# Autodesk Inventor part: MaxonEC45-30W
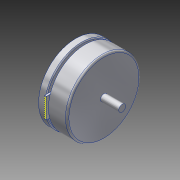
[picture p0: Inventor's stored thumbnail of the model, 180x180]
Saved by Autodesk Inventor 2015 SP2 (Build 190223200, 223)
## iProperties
Created: 2012-07
Part Number: MaxonEC45-30W
Material: Aluminium 6061
Document SubType Name: Modeling
Designer: rYan
Density: 2.71 g/cm^3
Mass: 63.84 g
Surface Area: 62.1715 cm^2
Volume: 23.5572 cm^3
Categories: <MemberInstance><Categories><Category DisplayName="" Mnemonic="CABLEANDHARNESS" InternalName="e4a7e005-5e42-4d16-b293-125e7f0d0512"><Category DisplayName="" Mne
Appearance: Aluminium - flach
GlobalPropertyList: <PropertyList/>
Author: rYan
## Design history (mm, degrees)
sketch "Skizze1"
  geometry: L1 (-3.2, 2)-(-3.2, 6); L2 (-3.2, 6)-(0, 6); L3 (0, 6)-(0, 21.6); L4 (16.4, 21.35)-(16.4, 2); L5 (-10, 0)-(27, 0); L6 (-17.4, 0)-(34.4, 0) reference; L7 (0, 21.6)-(4, 21.6); L8 (4, 21.6)-(4, 18.6); L9 (4, 18.6)-(5.5, 18.6); L10 (5.5, 18.6)-(5.5, 21.35); L11 (5.5, 21.35)-(16.4, 21.35); L12 (-3.2, 2)-(-10, 2); L13 (-10, 2)-(-10, 0); L14 (16.4, 2)-(27, 2); L15 (27, 2)-(27, 0); 1 further point
  constraints: 28 end point, 6 parallel, 6 perpendicular, 3 point on line, 1 collinear, 1 vertical
  dimensions: "d2" = 12 diameter of L2 L5; "d5" = 3.2 distance between parallel lines of L1 L3; "d6" = 16.4 distance between parallel lines of L4 L3; "d7" = 4 distance between parallel lines of L3 L8; "d8" = 1.5 distance between parallel lines of L10 L8; "d9" = 43.2 diameter of L7 L5; "d10" = 42.7 diameter of L11 L5; "d11" = 3 distance between parallel lines of L9 L7; "d44" = 10 distance between parallel lines of L3 L13; "d45" = 4 diameter of L12 L5; "d46" = 27 distance between parallel lines of L15 L3; "d47" = 4 diameter of L14 L5
revolve "Umdrehung1" sketch "Skizze1" stored, may be unused: angle "d12" = 90 deg
fillet "Rundung1" dims "d13" = 1
chamfer "Fase1" distance "d14" = 0.5; stored, may be unused: second distance "d15" = 2, angle "d16" = 45 deg
sketch "Skizze2"
  geometry: C1 r 6 at (0, 0) reference; C2 r 5 at (0, 0); C3 r 2 at (0, 0) reference; C4 r 2 at (0, 0); 1 further point
  constraints: 2 centre point, 2 coincident, 1 concentric
  dimensions: "d17" = 1 radial gap between concentric circles of C1 C2
extrude "Extrusion3" cut sketch "Skizze2" distance "d48" = 1; taper "d49" = 0 deg
sketch "Skizze4" dims "d27" = 22
  geometry: L1 (0, 30.32)-(0, -30.72) reference; 3 further points
  constraints: 1 coincident, 1 point on line, 1 vertical alignment, 2 other
hole "Bohrung2" sketch "Skizze4" at (0, 11) diameter "d29" = 2.459; stored, may be unused: countersink angle "d33" = 82 deg, drill point angle "d35" = 118 deg; dims "d30" = 6, "d31" = 3.023, "d32" = 2, "d34" = 3.9
pattern_circular "Runde Anordnung2" dims angle "d51" = 360 deg
sketch "Skizze5"
  geometry: L1 (0, -30.72)-(0, 30.32) reference; L2 (-6, -17.606)-(-6, -22); L3 (-6, -22)-(6, -22); L4 (6, -22)-(6, -17.606); A1 r 18.6 centre (0, 0) between (-6, -17.606) and (6, -17.606) reference; A2 r 18.6 centre (0, 0) between (-6, -17.606) and (6, -17.606); 1 further point
  constraints: 6 end point, 4 point on circle, 2 parallel, 1 centre point, 1 coincident, 1 perpendicular, 1 other
  dimensions: "d39" = 22 distance from line of L3 point (0, 0); "d40" = 12 distance of L2.end L3.end
extrude "Extrusion2" join sketch "Skizze5" distance "d41" = 1; taper "d42" = 0 deg
sketch "Skizze6"
  geometry: L1 (0, 12)-(0, 0) reference; L2 (0, 0)-(1, 0) reference; L3 (1, 12)-(1, 0) reference; L4 (0, 12)-(1, 12) reference; L5 (0.5, 12)-(0.5, 0); L6 (0, 6)-(1, 6); 3 further points
  constraints: 5 midpoint, 4 end point, 1 point on line
  dimensions: "d43" = 1 distance from line of L2 point (0.5, 1)
  node "Projizierte Kontur1"
node "1"
node "2"
node "3"
node "4"
node "5"
node "6"
node "7"
node "8"
node "9"
node "10"
node "11"
node "Volumenkörper1"
